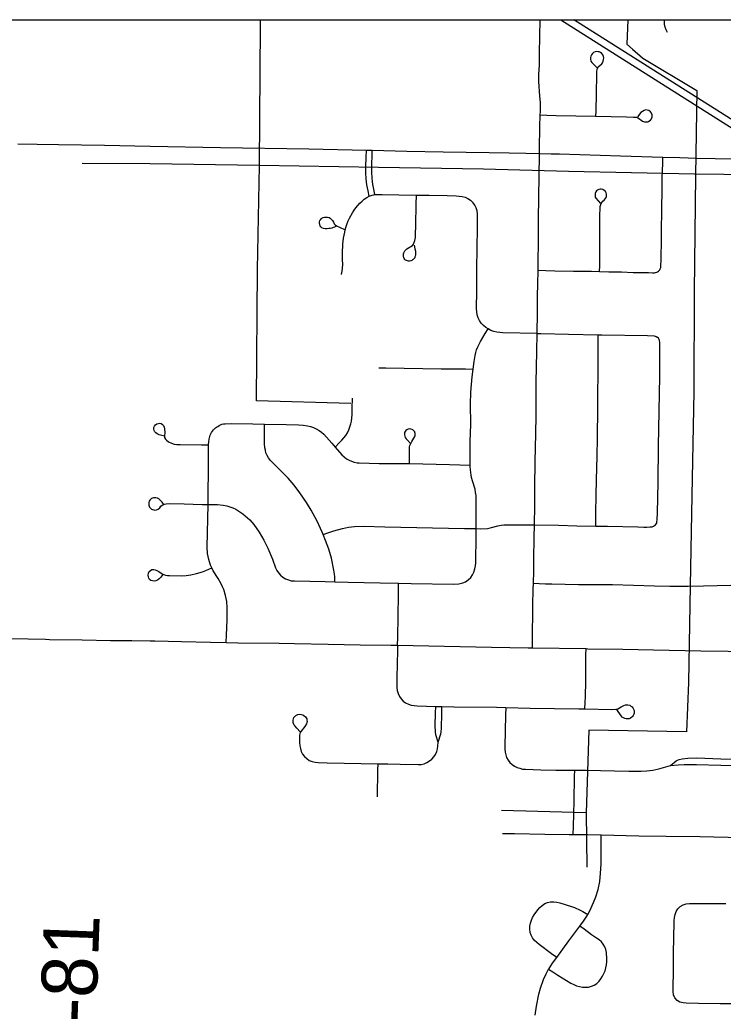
# Model space of a CAD drawing. Extents: x 0 to 680, y 0 to 834.
# Drawn here: x 268.33 to 295.82, y 355.35 to 394.07 of the extents above; entities that cross this region are included whole.
import ezdxf

# ---------------------------------------------------------------- set-up
doc = ezdxf.new("R2010")
doc.units = 0
for name, color, linetype in [('GM_X_City_Street', 7, 'Continuous'), ('GM_X_County_Road', 7, 'Continuous'), ('GM_X_Interstate_Route', 7, 'Continuous'), ('GM_X_Minor_River', 7, 'Continuous'), ('GM_X_Rail_Line', 7, 'Continuous'), ('GM_X_Township_Road', 7, 'Continuous'), ('GM_X_Township_Road_Text', 7, 'Continuous')]:
    doc.layers.add(name, color=color, linetype=linetype)

msp = doc.modelspace()

# ---------------------------------------------------------------- linework, layer by layer
at = {"layer": 'GM_X_City_Street'}
for points in [[(288.362, 369.54), (288.364, 369.793), (288.381, 371.223), (288.394, 371.817), (288.401, 372.062), (288.414, 372.53), (288.423, 373.007), (288.436, 373.842), (288.445, 374.343), (288.459, 375.096), (288.463, 375.821), (288.474, 376.822), (288.496, 377.895), (288.507, 378.617), (288.514, 379.906), (288.53, 381.113), (288.545, 381.822), (288.562, 382.644), (288.566, 383.283), (288.574, 383.746), (288.581, 384.285), (288.602, 385.723), (288.604, 386.236), (288.613, 387.184), (288.621, 387.925), (288.639, 388.849), (288.642, 389.034), (288.657, 389.893), (288.67, 390.358), (288.674, 390.487), (288.674, 390.838), (288.656, 391.081), (288.616, 391.661), (288.619, 391.795), (288.619, 391.94), (288.641, 392.313), (288.637, 392.769), (288.663, 394.069)], [(293.647, 393.57), (293.592, 393.674), (293.552, 393.784), (293.528, 393.899), (293.518, 394.016), (293.518, 394.069)], [(290.846, 390.3), (290.85, 390.498), (290.862, 391.197), (290.873, 391.923), (290.882, 392.043), (290.892, 392.144), (290.913, 392.194), (290.935, 392.229), (291.072, 392.345), (291.102, 392.391), (291.126, 392.452), (291.144, 392.515), (291.149, 392.572), (291.144, 392.633), (291.117, 392.702), (291.075, 392.754), (291.017, 392.796), (290.97, 392.815), (290.929, 392.824), (290.863, 392.828), (290.81, 392.815), (290.754, 392.79), (290.71, 392.75), (290.673, 392.708), (290.648, 392.647), (290.633, 392.601), (290.632, 392.528), (290.651, 392.461), (290.689, 392.4), (290.73, 392.353), (290.886, 392.2)], [(288.67, 390.358), (288.931, 390.345), (289.286, 390.328), (290.822, 390.301), (290.846, 390.3), (292.036, 390.278), (292.311, 390.272), (292.432, 390.262), (292.48, 390.246), (292.545, 390.201), (292.61, 390.146), (292.67, 390.113), (292.743, 390.091), (292.81, 390.081), (292.867, 390.089), (292.916, 390.105), (292.973, 390.148), (293.018, 390.207), (293.038, 390.279), (293.038, 390.356), (293.018, 390.425), (292.981, 390.482), (292.908, 390.531), (292.849, 390.545), (292.792, 390.548), (292.726, 390.532), (292.665, 390.492), (292.604, 390.445), (292.474, 390.283)], [(281.981, 387.178), (281.941, 387.395), (281.898, 387.628), (281.867, 387.863), (281.851, 388.099), (281.85, 388.335), (281.867, 388.69), (281.88, 388.981)], [(282.206, 387.246), (282.15, 387.521), (282.125, 387.639), (282.108, 387.759), (282.096, 387.879), (282.087, 388.12), (282.09, 388.482), (282.098, 388.722), (282.105, 388.975)], [(293.284, 384.251), (293.312, 384.274), (293.34, 384.309), (293.36, 384.345), (293.374, 384.396), (293.383, 384.467), (293.391, 384.689), (293.405, 385.524), (293.41, 386.111), (293.418, 386.344), (293.422, 386.701), (293.432, 387.411), (293.438, 387.885), (293.453, 388.468), (293.458, 388.708)], [(280.901, 384.117), (280.925, 384.252), (280.949, 384.5), (280.947, 384.72), (280.947, 384.955), (280.96, 385.307), (280.984, 385.541), (281.027, 385.772), (281.05, 385.861), (281.086, 386), (281.124, 386.111), (281.169, 386.22), (281.22, 386.325), (281.335, 386.531), (281.398, 386.63), (281.467, 386.725), (281.542, 386.815), (281.622, 386.902), (281.705, 386.985), (281.794, 387.062), (281.89, 387.129), (281.981, 387.178), (282.097, 387.223)], [(282.097, 387.223), (282.167, 387.24), (282.206, 387.246), (282.488, 387.251), (283.14, 387.233), (283.83, 387.225), (284.322, 387.219), (285.033, 387.209), (285.389, 387.197), (285.506, 387.187), (285.622, 387.169), (285.735, 387.14), (285.843, 387.092), (285.94, 387.025), (286.041, 386.92)], [(283.74, 385.271), (283.77, 385.125), (283.789, 385.037), (283.795, 384.955), (283.795, 384.89), (283.787, 384.842), (283.774, 384.807), (283.763, 384.779), (283.741, 384.747), (283.706, 384.712), (283.679, 384.692), (283.647, 384.669), (283.607, 384.654), (283.563, 384.646), (283.519, 384.647), (283.481, 384.654), (283.442, 384.667), (283.409, 384.688), (283.381, 384.714), (283.355, 384.744), (283.337, 384.782), (283.329, 384.817), (283.321, 384.86), (283.322, 384.9), (283.327, 384.934), (283.34, 384.973), (283.36, 385.014), (283.381, 385.047), (283.402, 385.071), (283.425, 385.098), (283.461, 385.126), (283.671, 385.258), (283.715, 385.302), (283.734, 385.345), (283.77, 385.456), (283.789, 385.572), (283.797, 385.689), (283.807, 386.042), (283.816, 386.864), (283.83, 387.225)], [(290.99, 384.242), (290.993, 384.467), (291, 385.043), (290.996, 385.404), (290.995, 385.886), (291.002, 386.365), (291.014, 386.784), (291.03, 386.852), (291.049, 386.899), (291.076, 386.936), (291.118, 386.982), (291.169, 387.03), (291.208, 387.084), (291.238, 387.134), (291.251, 387.164), (291.259, 387.202), (291.257, 387.257), (291.246, 387.308), (291.213, 387.363), (291.169, 387.406), (291.118, 387.436), (291.055, 387.453), (291.009, 387.453), (290.956, 387.444), (290.904, 387.418), (290.867, 387.388), (290.844, 387.357), (290.822, 387.32), (290.812, 387.284), (290.808, 387.24), (290.811, 387.193), (290.82, 387.145), (290.838, 387.104), (291.019, 386.895)], [(288.545, 381.822), (287.207, 381.85), (287.087, 381.855), (286.968, 381.866), (286.852, 381.891), (286.74, 381.933), (286.629, 381.995), (286.537, 382.058), (286.445, 382.136), (286.364, 382.224), (286.296, 382.322), (286.243, 382.429), (286.207, 382.542), (286.185, 382.66), (286.175, 382.779), (286.173, 382.899), (286.185, 383.377), (286.196, 384.334), (286.207, 385.162), (286.21, 385.412), (286.213, 385.703), (286.217, 386.008), (286.221, 386.367), (286.217, 386.487), (286.202, 386.606), (286.17, 386.72), (286.113, 386.825), (286.041, 386.92)], [(280.682, 385.999), (280.628, 385.971), (280.578, 385.952), (280.526, 385.937), (280.465, 385.924), (280.404, 385.913), (280.332, 385.902), (280.265, 385.904), (280.198, 385.915), (280.139, 385.941), (280.094, 385.98), (280.066, 386.026), (280.051, 386.078), (280.046, 386.134), (280.048, 386.175), (280.061, 386.225), (280.081, 386.258), (280.111, 386.293), (280.139, 386.319), (280.181, 386.342), (280.236, 386.357), (280.298, 386.366), (280.359, 386.358), (280.415, 386.344), (280.458, 386.316), (280.506, 386.275), (280.545, 386.225), (280.584, 386.168), (280.622, 386.107), (280.66, 386.056), (280.705, 386.017), (280.818, 385.966), (281.05, 385.861)], [(288.581, 384.285), (288.888, 384.278), (289.24, 384.269), (289.968, 384.251), (290.672, 384.252), (290.99, 384.242), (291.347, 384.232), (291.839, 384.22), (292.297, 384.205), (292.894, 384.195), (293.049, 384.188), (293.132, 384.193), (293.177, 384.202), (293.219, 384.214), (293.25, 384.228), (293.284, 384.251)], [(275.692, 375.143), (276.055, 375.141), (276.282, 375.109), (276.42, 375.082), (276.541, 375.047), (276.659, 375.007), (276.773, 374.956), (276.853, 374.91), (277.05, 374.773), (277.233, 374.619), (277.318, 374.535), (277.473, 374.352), (277.679, 374.058), (277.863, 373.75), (278.024, 373.429), (278.207, 372.998), (278.324, 372.671), (278.375, 372.563), (278.442, 372.464), (278.521, 372.374), (278.612, 372.297), (278.714, 372.235), (278.825, 372.19), (278.942, 372.163), (279.061, 372.152), (280.258, 372.129), (280.647, 372.121), (281.169, 372.102), (282.409, 372.083), (283.127, 372.06), (283.621, 372.052), (285.281, 372.029), (285.489, 372.041), (285.642, 372.073), (285.747, 372.124), (285.853, 372.194), (285.951, 372.293), (286.018, 372.391), (286.077, 372.501), (286.113, 372.621), (286.139, 372.737), (286.149, 372.857), (286.158, 373.931), (286.162, 374.205), (286.17, 374.769), (286.168, 375.365), (286.16, 375.487), (286.144, 375.608), (286.12, 375.733), (286.026, 376.061), (285.982, 376.197), (285.963, 376.289), (285.937, 376.49), (285.924, 376.629), (285.924, 376.68), (285.935, 377.588), (285.95, 378.276), (285.939, 379.053), (285.959, 379.527), (286.008, 380.125), (286.045, 380.43), (286.08, 380.719), (286.121, 380.955), (286.148, 381.071), (286.182, 381.185), (286.225, 381.296), (286.338, 381.507), (286.522, 381.816), (286.629, 381.995)], [(288.545, 381.822), (288.694, 381.819), (289.775, 381.796), (290.928, 381.772), (291.077, 381.769), (292.865, 381.739), (293.124, 381.726), (293.193, 381.706), (293.241, 381.681)], [(290.845, 374.297), (290.843, 374.506), (290.841, 374.745), (290.853, 375.553), (290.867, 376.031), (290.881, 376.618), (290.888, 376.975), (290.905, 377.788), (290.919, 378.86), (290.921, 378.979), (290.927, 380.719), (290.928, 380.833), (290.929, 380.95), (290.931, 381.188), (290.933, 381.42), (290.931, 381.521), (290.928, 381.772)], [(293.176, 374.339), (293.201, 374.378), (293.218, 374.416), (293.227, 374.463), (293.238, 374.542), (293.25, 374.811), (293.274, 375.995), (293.288, 377.417), (293.338, 380.148), (293.346, 381.207), (293.344, 381.461), (293.334, 381.541), (293.32, 381.589), (293.289, 381.637), (293.241, 381.681)], [(282.364, 380.483), (282.639, 380.481), (284.793, 380.441), (285.751, 380.433), (286.045, 380.43)], [(280.655, 377.376), (280.83, 377.558), (280.916, 377.646), (280.996, 377.739), (281.068, 377.839), (281.133, 377.944), (281.188, 378.054), (281.233, 378.168), (281.264, 378.286), (281.295, 378.389), (281.311, 378.512), (281.315, 378.66), (281.319, 378.906), (281.331, 379.296)], [(273.98, 377.806), (273.784, 377.862), (273.705, 377.901), (273.645, 377.944), (273.61, 377.976), (273.585, 378.025), (273.569, 378.085), (273.574, 378.148), (273.596, 378.202), (273.636, 378.254), (273.692, 378.288), (273.746, 378.308), (273.8, 378.314), (273.86, 378.3), (273.91, 378.267), (273.945, 378.226), (273.979, 378.162), (273.992, 378.094), (273.994, 377.949), (273.988, 377.824), (273.988, 377.782), (273.989, 377.755), (274.024, 377.694), (274.058, 377.655), (274.148, 377.581), (274.26, 377.531), (274.361, 377.5), (274.47, 377.485), (274.594, 377.485), (275.43, 377.468), (275.707, 377.464)], [(276.398, 369.75), (276.409, 370.038), (276.431, 370.638), (276.43, 371.114), (276.417, 371.353), (276.4, 371.472), (276.374, 371.589), (276.302, 371.818), (276.256, 371.929), (276.204, 372.037), (276.081, 372.243), (275.891, 372.549), (275.832, 372.665), (275.79, 372.766), (275.717, 372.995), (275.689, 373.112), (275.67, 373.23), (275.655, 373.469), (275.692, 375.143), (275.712, 376.893), (275.707, 377.464), (275.715, 377.584), (275.727, 377.689), (275.752, 377.798), (275.769, 377.847), (275.793, 377.903), (275.825, 377.955), (275.856, 378.003), (275.898, 378.053), (275.94, 378.096), (275.985, 378.131), (276.021, 378.16), (276.069, 378.191), (276.117, 378.22), (276.178, 378.249), (276.232, 378.27), (276.295, 378.284), (276.358, 378.29), (276.596, 378.301), (277.432, 378.291), (277.893, 378.283), (278.744, 378.257), (279.218, 378.25), (279.407, 378.238), (279.568, 378.214), (279.692, 378.179), (279.804, 378.141), (279.913, 378.091), (280.024, 378.032), (280.124, 377.962), (280.215, 377.885), (280.529, 377.53), (280.655, 377.376), (280.919, 377.074), (281.004, 376.998), (281.092, 376.929), (281.199, 376.874), (281.293, 376.831), (281.393, 376.798), (281.509, 376.771), (281.598, 376.761), (282.375, 376.744), (283.445, 376.737), (283.562, 376.735), (285.124, 376.696), (285.924, 376.68)], [(280.647, 372.121), (280.641, 372.316), (280.627, 372.414), (280.607, 372.573), (280.507, 373.046), (280.405, 373.391), (280.283, 373.728), (280.188, 373.966), (280.151, 374.061), (279.947, 374.493), (279.721, 374.912), (279.536, 375.218), (279.272, 375.601), (279.051, 375.896), (278.819, 376.167), (278.474, 376.505), (278.128, 376.86), (278.054, 376.959), (277.998, 377.05), (277.952, 377.158), (277.927, 377.257), (277.907, 377.35), (277.896, 377.508), (277.898, 378.049), (277.893, 378.283)], [(283.562, 376.735), (283.558, 377.041), (283.555, 377.271), (283.565, 377.387), (283.576, 377.44), (283.6, 377.498), (283.655, 377.599), (283.731, 377.727), (283.766, 377.792), (283.779, 377.839), (283.783, 377.884), (283.781, 377.917), (283.774, 377.947), (283.762, 377.974), (283.735, 378.011), (283.711, 378.034), (283.686, 378.052), (283.658, 378.07), (283.618, 378.083), (283.573, 378.09), (283.51, 378.084), (283.457, 378.061), (283.417, 378.028), (283.386, 377.987), (283.37, 377.953), (283.36, 377.913), (283.359, 377.859), (283.371, 377.81), (283.396, 377.755), (283.435, 377.698), (283.484, 377.646), (283.599, 377.521)], [(273.946, 375.149), (273.894, 375.228), (273.832, 375.301), (273.766, 375.355), (273.712, 375.387), (273.653, 375.402), (273.587, 375.405), (273.55, 375.402), (273.511, 375.391), (273.476, 375.374), (273.436, 375.34), (273.407, 375.305), (273.387, 375.267), (273.374, 375.219), (273.37, 375.166), (273.374, 375.119), (273.386, 375.074), (273.404, 375.032), (273.433, 374.996), (273.478, 374.96), (273.511, 374.946), (273.566, 374.925), (273.613, 374.919), (273.671, 374.929), (273.742, 374.96), (273.803, 375.015), (273.846, 375.069), (273.893, 375.11), (273.933, 375.132), (273.98, 375.152), (274.046, 375.164), (274.165, 375.175), (274.757, 375.168), (275.46, 375.143), (275.692, 375.143)], [(280.188, 373.966), (280.372, 374.031), (280.597, 374.11), (280.942, 374.205), (281.176, 374.25), (281.413, 374.275), (281.77, 374.287), (282.601, 374.263), (285.706, 374.205), (286.162, 374.205), (286.349, 374.193), (286.604, 374.204), (286.767, 374.239), (287.006, 374.312), (287.135, 374.336), (287.242, 374.347), (287.361, 374.345), (288.315, 374.345), (288.445, 374.343), (289.387, 374.33), (290.101, 374.312), (290.845, 374.297), (291.293, 374.288), (292.484, 374.264), (292.72, 374.259), (292.837, 374.259), (292.954, 374.264), (293.038, 374.271), (293.095, 374.288), (293.139, 374.315), (293.176, 374.339)], [(273.927, 372.402), (273.847, 372.307), (273.779, 372.233), (273.713, 372.187), (273.651, 372.158), (273.585, 372.144), (273.519, 372.151), (273.458, 372.173), (273.406, 372.211), (273.373, 372.258), (273.355, 372.315), (273.346, 372.374), (273.36, 372.458), (273.391, 372.518), (273.439, 372.562), (273.494, 372.595), (273.567, 372.602), (273.628, 372.588), (273.692, 372.566), (273.77, 372.518), (273.9, 372.427), (273.955, 372.4), (274.025, 372.379), (274.098, 372.368), (274.176, 372.361), (274.645, 372.352), (274.832, 372.366), (275.014, 372.388), (275.242, 372.439), (275.475, 372.512), (275.602, 372.566), (275.832, 372.665)], [(283.092, 369.639), (283.098, 369.946), (283.113, 370.782), (283.128, 371.616), (283.127, 371.855), (283.127, 372.06)], [(288.401, 372.062), (288.628, 372.051), (288.88, 372.045), (289.116, 372.038), (290.165, 372.013), (290.896, 372.019), (291.486, 372.009), (293.135, 371.964), (293.73, 371.946), (294.445, 371.947), (295.041, 371.956), (296.113, 371.991)], [(283.092, 369.639), (283.087, 369.297), (283.083, 369.059), (283.061, 368.225), (283.065, 367.986), (283.08, 367.868), (283.112, 367.753), (283.163, 367.646), (283.232, 367.549), (283.314, 367.462), (283.408, 367.39), (283.515, 367.337), (283.629, 367.302), (283.865, 367.27), (284.223, 367.259), (284.588, 367.252), (284.829, 367.248), (285.295, 367.239), (286.961, 367.217), (287.319, 367.21), (288.273, 367.19), (290.18, 367.162), (290.417, 367.161), (291.47, 367.132), (291.627, 367.14), (291.665, 367.148), (291.698, 367.164), (291.762, 367.201), (291.83, 367.239), (291.931, 367.285), (292.006, 367.308), (292.09, 367.311), (292.163, 367.295), (292.213, 367.268), (292.259, 367.236), (292.292, 367.195), (292.318, 367.148), (292.337, 367.093), (292.341, 367.044), (292.332, 366.987), (292.322, 366.946), (292.3, 366.903), (292.273, 366.859), (292.241, 366.827), (292.198, 366.797), (292.139, 366.772), (292.082, 366.763), (292.024, 366.764), (291.972, 366.778), (291.916, 366.804), (291.87, 366.838), (291.832, 366.882), (291.656, 367.131)], [(290.417, 367.161), (290.425, 367.399), (290.432, 367.634), (290.446, 368.228), (290.454, 368.819), (290.456, 369.262), (290.457, 369.509)], [(284.674, 365.854), (284.59, 366.147), (284.571, 366.258), (284.563, 366.502), (284.579, 366.989), (284.588, 367.252)], [(284.674, 365.854), (284.786, 366.178), (284.799, 366.253), (284.812, 366.404), (284.822, 366.98), (284.829, 367.248)], [(287.319, 367.21), (287.312, 366.915), (287.279, 365.692), (287.28, 365.584), (287.293, 365.469), (287.318, 365.357), (287.356, 365.251), (287.411, 365.153), (287.482, 365.065), (287.565, 364.987), (287.659, 364.923), (287.761, 364.873), (287.87, 364.835), (287.981, 364.808), (288.094, 364.797), (288.688, 364.779), (289.28, 364.766), (290.014, 364.765), (290.469, 364.764), (292.133, 364.718), (292.606, 364.718), (292.839, 364.732), (293.071, 364.767), (293.301, 364.818), (293.755, 364.951)], [(279.289, 366.263), (279.152, 366.398), (279.086, 366.476), (279.052, 366.526), (279.024, 366.586), (279.014, 366.621), (279.008, 366.669), (279.01, 366.715), (279.022, 366.767), (279.046, 366.823), (279.076, 366.862), (279.117, 366.898), (279.191, 366.932), (279.263, 366.948), (279.342, 366.942), (279.394, 366.926), (279.436, 366.902), (279.494, 366.851), (279.524, 366.809), (279.542, 366.769), (279.553, 366.719), (279.556, 366.667), (279.55, 366.618), (279.53, 366.568), (279.47, 366.466), (279.323, 366.287), (279.291, 366.239), (279.272, 366.18), (279.261, 366.13), (279.255, 366.065), (279.26, 365.838), (279.271, 365.719), (279.294, 365.603), (279.331, 365.491), (279.385, 365.386), (279.459, 365.293), (279.546, 365.212), (279.644, 365.146), (279.753, 365.1), (279.869, 365.072), (279.987, 365.059), (280.343, 365.05), (282.332, 365.012), (282.715, 365.005), (283.189, 364.998), (283.901, 364.978), (284.019, 364.988), (284.134, 365.016), (284.243, 365.063), (284.345, 365.123), (284.437, 365.198), (284.514, 365.288), (284.575, 365.38), (284.623, 365.49), (284.654, 365.59), (284.668, 365.704), (284.674, 365.854)], [(293.755, 364.951), (293.974, 365.123), (294.03, 365.151), (294.095, 365.174), (294.213, 365.205), (294.437, 365.23), (294.788, 365.238), (295.724, 365.209), (296.543, 365.198), (296.798, 365.195)], [(282.307, 363.723), (282.322, 364.761), (282.332, 365.012)], [(289.96, 362.252), (289.969, 362.561), (289.995, 363.546), (290.011, 364.515), (290.014, 364.765)], [(293.755, 364.951), (294.057, 364.971), (294.295, 364.986), (294.775, 364.979), (295.73, 364.958), (296.534, 364.945), (296.797, 364.942)], [(287.193, 362.288), (287.667, 362.284), (288.851, 362.26), (289.799, 362.254), (289.96, 362.252), (290.511, 362.247), (291.054, 362.235), (292.526, 362.203), (293.594, 362.179), (294.898, 362.166), (296.557, 362.136), (296.755, 362.132)], [(288.464, 355.189), (288.516, 355.545), (288.61, 356.017), (288.675, 356.25), (288.799, 356.59), (288.899, 356.81), (288.994, 356.984), (289.015, 357.022), (289.145, 357.226), (289.31, 357.448), (289.787, 358.092), (290.214, 358.673), (290.354, 358.862), (290.484, 359.06), (290.524, 359.131), (290.6, 359.266), (290.751, 359.588), (290.837, 359.809), (290.93, 360.105), (290.993, 360.418), (291.028, 360.734), (291.043, 361.092), (291.05, 361.449), (291.047, 361.928), (291.05, 362.048), (291.054, 362.235)], [(289.31, 357.448), (289.112, 357.594), (288.626, 357.952), (288.532, 358.027), (288.446, 358.112), (288.371, 358.208), (288.312, 358.313), (288.272, 358.426), (288.256, 358.546), (288.262, 358.666), (288.285, 358.785), (288.322, 358.9), (288.372, 359.01), (288.433, 359.115), (288.577, 359.309), (288.657, 359.399), (288.746, 359.482), (288.846, 359.549), (288.956, 359.596), (289.074, 359.619), (289.195, 359.622), (289.315, 359.608), (289.433, 359.58), (289.895, 359.438), (290.008, 359.396), (290.227, 359.294), (290.333, 359.236), (290.524, 359.131)], [(296.491, 355.641), (295.694, 355.64), (294.854, 355.652), (294.372, 355.661), (294.248, 355.672), (294.124, 355.704), (294.012, 355.769), (293.926, 355.868), (293.876, 355.986), (293.856, 356.112), (293.856, 356.357), (293.869, 356.836), (293.879, 357.678), (293.894, 358.158), (293.903, 358.88), (293.913, 359.002), (293.935, 359.126), (293.978, 359.245), (294.046, 359.352), (294.138, 359.441), (294.248, 359.505), (294.369, 359.545), (294.494, 359.56), (295.578, 359.55), (295.924, 359.55)], [(288.994, 356.984), (289.16, 356.881), (289.362, 356.755), (289.869, 356.442), (289.975, 356.388), (290.086, 356.345), (290.201, 356.313), (290.318, 356.291), (290.437, 356.282), (290.556, 356.292), (290.671, 356.32), (290.781, 356.368), (290.879, 356.434), (290.965, 356.516), (291.038, 356.611), (291.1, 356.712), (291.154, 356.819), (291.2, 356.929), (291.237, 357.042), (291.259, 357.159), (291.27, 357.278), (291.27, 357.397), (291.252, 357.635), (291.231, 357.752), (291.192, 357.864), (291.133, 357.968), (291.056, 358.059), (290.967, 358.138), (290.87, 358.207), (290.669, 358.336), (290.382, 358.548), (290.214, 358.673)]]:
    msp.add_lwpolyline(points, dxfattribs=at)
at = {"layer": 'GM_X_County_Road'}
for points in [[(268.249, 389.232), (269.01, 389.213), (269.846, 389.2), (271.636, 389.178), (273.425, 389.14), (276.17, 389.089), (279.631, 389.026), (281.88, 388.981)], [(281.88, 388.981), (282.105, 388.975), (283.449, 388.94), (284.881, 388.916), (286.671, 388.881), (287.457, 388.869), (288.103, 388.86), (288.639, 388.849)], [(288.639, 388.849), (289.093, 388.839), (289.415, 388.832), (291.801, 388.754), (293.458, 388.708)], [(293.458, 388.708), (294.121, 388.69), (294.779, 388.672), (295.499, 388.655), (296.214, 388.639)]]:
    msp.add_lwpolyline(points, dxfattribs=at)
at = {"layer": 'GM_X_Interstate_Route'}
msp.add_lwpolyline([(44.693, 394.069), (374.693, 394.069), (374.693, 64.069), (44.693, 64.069)], close=True, dxfattribs=at)
at = {"layer": 'GM_X_Minor_River'}
for points in [[(281.27, 379.081), (277.587, 379.194), (277.626, 384.317), (277.703, 388.373), (277.734, 393.831), (277.734, 394.069)], [(292.088, 394.069), (292.055, 393.123), (292.27, 392.929), (292.671, 392.571), (294.788, 391.305), (294.74, 387.993), (294.683, 383.454), (294.667, 379.557)], [(310.083, 385.865), (308.998, 387.768), (305.241, 387.882), (301.862, 387.917), (298.877, 387.958), (295.848, 388.03), (294.69, 388.035), (289.775, 388.145), (286.456, 388.236), (282.349, 388.3), (277.703, 388.373), (273.407, 388.44), (270.771, 388.46)], [(294.667, 379.557), (294.59, 375.472), (294.523, 371.97), (294.466, 368.191), (294.385, 366.266), (290.57, 366.323), (290.465, 363.1), (290.483, 360.968)], [(290.465, 363.1), (287.16, 363.191)]]:
    msp.add_lwpolyline(points, dxfattribs=at)
at = {"layer": 'GM_X_Rail_Line'}
for points in [[(289.467, 394.069), (307.515, 382.668), (328.281, 369.679), (328.409, 358.781), (332.297, 358.476)], [(332.297, 358.476), (331.554, 365.995), (331.138, 367.685), (329.743, 369.173), (306.922, 383.362), (289.987, 394.069)]]:
    msp.add_lwpolyline(points, dxfattribs=at)
at = {"layer": 'GM_X_Township_Road'}
msp.add_line((288.362, 369.54), (290.457, 369.509), dxfattribs=at)
for points in [[(267.976, 369.908), (269.338, 369.874), (269.494, 369.87), (270.769, 369.85), (271.881, 369.832), (271.982, 369.831), (272.083, 369.829), (272.716, 369.821), (273.421, 369.811), (273.611, 369.808), (274.648, 369.784), (275.78, 369.765), (276.398, 369.75)], [(276.398, 369.75), (276.854, 369.74), (278.466, 369.718), (279.063, 369.708), (280.376, 369.684), (281.629, 369.663), (282.824, 369.644), (283.092, 369.639)], [(283.092, 369.639), (286.762, 369.57), (288.195, 369.543), (288.362, 369.54)], [(290.457, 369.509), (290.523, 369.508), (291.896, 369.482), (293.09, 369.462), (294.941, 369.428), (296.016, 369.409), (296.612, 369.398), (296.801, 369.399)]]:
    msp.add_lwpolyline(points, dxfattribs=at)

# ---------------------------------------------------------------- texts
at = {"layer": 'GM_X_Township_Road_Text'}
msp.add_text('T-81', height=2.1818, rotation=87.9113, dxfattribs=at).set_placement((271.238, 353.092))

doc.saveas('drawing.dxf')
